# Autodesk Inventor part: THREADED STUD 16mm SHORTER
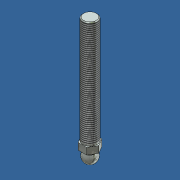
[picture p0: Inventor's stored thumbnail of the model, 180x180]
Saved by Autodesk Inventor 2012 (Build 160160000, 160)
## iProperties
Created: 2007-03
Part Number: THREADED STUD 16mm SHORTER
Document SubType Name: Modeling
Designer: Andy Moles
Material: Steel
Mass: 265.946 g
Surface Area: 89.9795 cm^2
Volume: 33.8784 cm^3
Density: 7.85 g/cm^3
Author: Andy Moles
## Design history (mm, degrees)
sketch "Sketch1"
  geometry: L1 (0, -7.5)-(0, 7.5); A1 r 7.5 centre (0, 0) between (0, -7.5) and (0, 7.5); 1 further point
  constraints: 2 end point, 2 point on circle, 1 centre point, 1 coincident, 1 midpoint, 1 vertical
  dimensions: "d5" = 15 distance of L1.start L1.end
revolve "Revolution1" sketch "Sketch1" stored, may be unused: angle "d1" = 90 deg
sketch "Sketch2"
  geometry: C1 r 6 at (0, 0); 1 further point
  constraints: 1 centre point, 1 coincident
  dimensions: "d2" = 12 diameter of C1
extrude "Extrusion1" join sketch "Sketch2" distance "d3" = 7; taper "d4" = 0 deg
sketch "Sketch3"
  geometry: L1 (-4.907, 8.5)-(4.907, 8.5); L2 (4.907, 8.5)-(9.815, 0); L3 (9.815, 0)-(4.907, -8.5); L4 (4.907, -8.5)-(-4.907, -8.5); L5 (-4.907, -8.5)-(-9.815, 0); L6 (-9.815, 0)-(-4.907, 8.5); C1 r 6 at (0, 0) reference; 1 further point
  constraints: 12 end point, 5 equal length, 1 horizontal, 1 horizontal alignment, 1 midpoint, 1 parallel, 1 vertical alignment
  dimensions: "d6" = 120 deg angle of L6 L5; "d7" = 120 deg angle of L1 L6; "d8" = 17 distance between parallel lines of L4 L1
extrude "Extrusion2" join sketch "Sketch3" distance "d9" = 7.5; taper "d10" = 0 deg
sketch "Sketch4"
  geometry: C1 r 8 at (0, 0); 1 further point
  constraints: 1 centre point, 1 coincident
  dimensions: "d11" = 16 diameter of C1
extrude "Extrusion3" join sketch "Sketch4" distance "d12" = 120.5; taper "d13" = 0 deg
thread "Thread1" dims "d14" = 148, "d15" = 2
chamfer "Chamfer1" distance "d16" = 1; stored, may be unused: second distance "d17" = 2, angle "d18" = 45 deg
body "Solid1"
